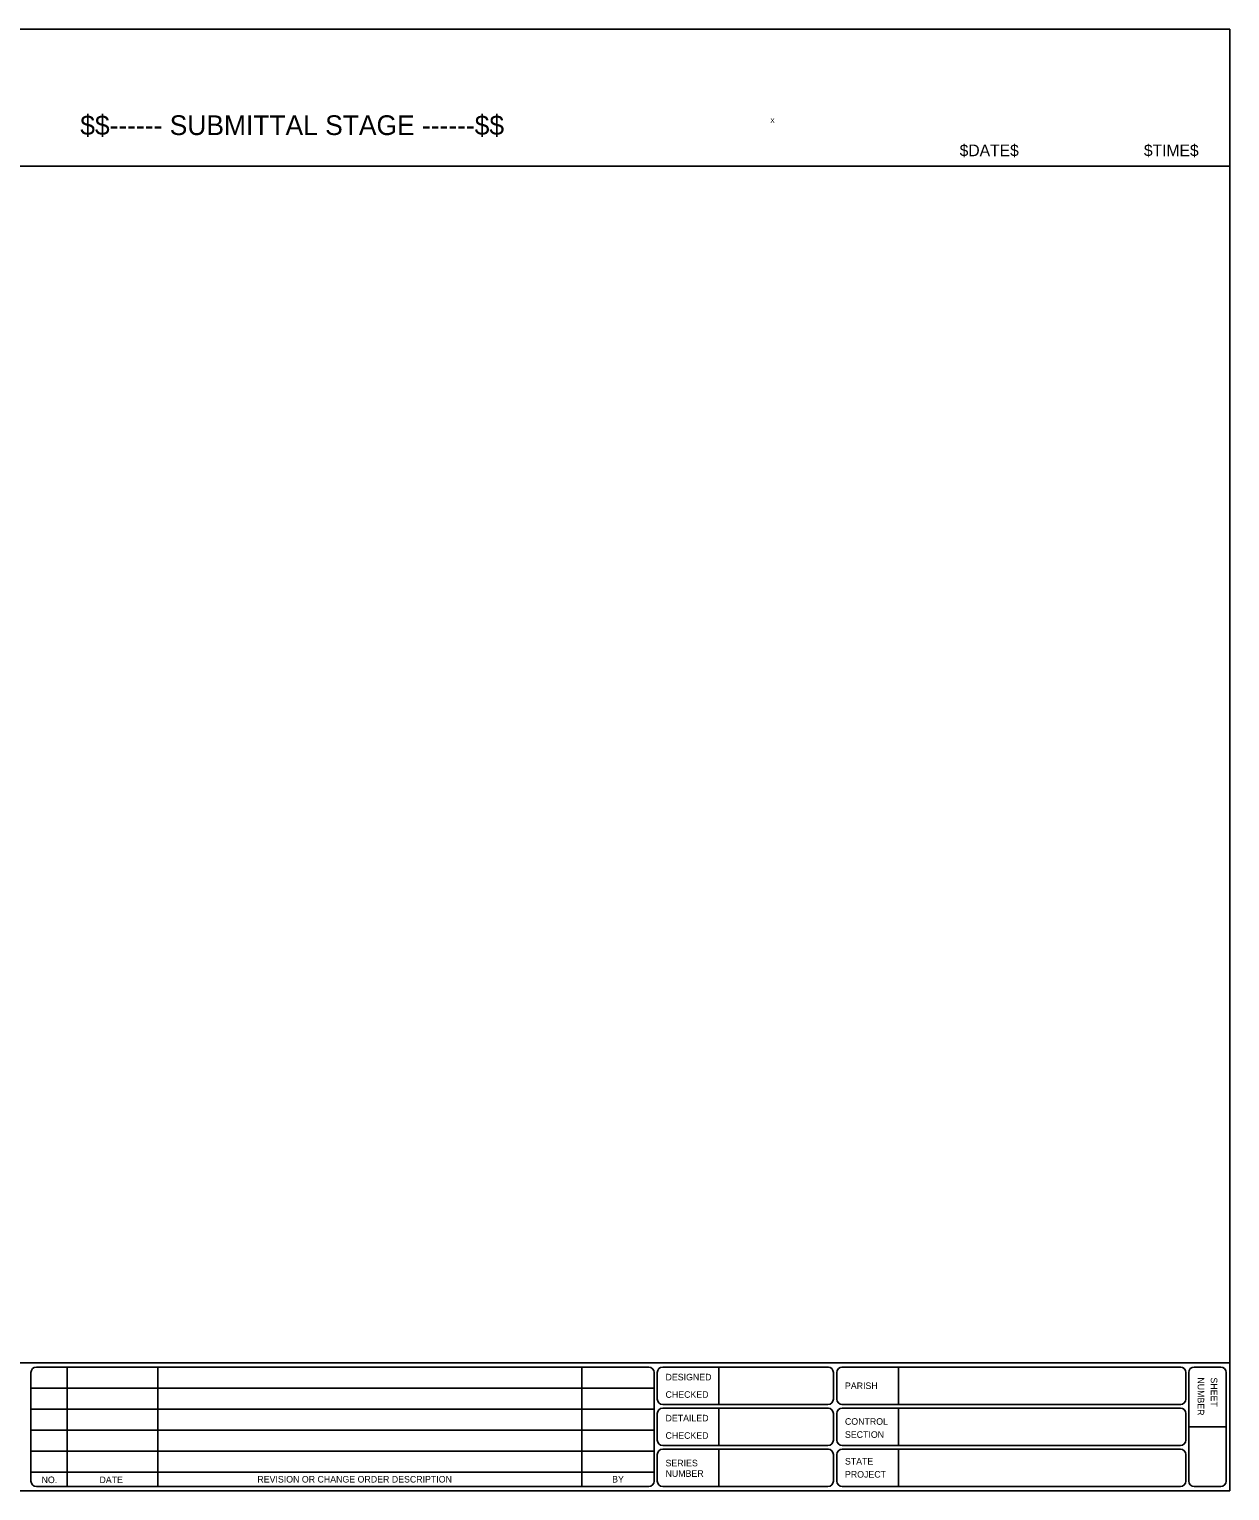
# Model space of a CAD drawing. Extents: x 0 to 1.75, y 0 to 1.33.
# Drawn here: x 0.655 to 1.75, y 0 to 1.333 of the extents above; entities that cross this region are included whole.
import ezdxf

# ---------------------------------------------------------------- set-up
doc = ezdxf.new("R2010")
doc.units = 0
for name, color, linetype in [('Construction Class', 7, 'Continuous'), ('Plot Border', 7, 'Continuous'), ('Sheet Border', 7, 'Continuous')]:
    doc.layers.add(name, color=color, linetype=linetype)

msp = doc.modelspace()

# ---------------------------------------------------------------- linework, layer by layer
at = {"layer": 'Construction Class'}
msp.add_line((1.3333, 1.25), (1.3333, 1.25), dxfattribs=at)
at = {"layer": 'Plot Border'}
msp.add_lwpolyline([(1.75, 0), (1.75, 1.3333), (0, 1.3333), (0, 0)], close=True, dxfattribs=at)
at = {"layer": 'Sheet Border'}
for p, q in [((1.75, 1.2083), (0, 1.2083)), ((1.75, 0), (1.75, 1.2083)), ((1.75, 0.1167), (0, 0.1167)), ((0.6568, 0.1079), (0.6568, 0.0088)), ((1.2202, 0.1128), (0.6618, 0.1128)), ((0.6898, 0.1128), (0.6898, 0.0039)), ((0.7724, 0.1128), (0.7724, 0.0039)), ((1.1591, 0.0039), (1.1591, 0.1128)), ((1.2251, 0.0088), (1.2251, 0.1078)), ((1.228, 0.0836), (1.228, 0.1079)), ((1.384, 0.1128), (1.233, 0.1128)), ((1.2841, 0.0787), (1.2841, 0.1128)), ((1.3886, 0.0836), (1.3886, 0.1079)), ((1.3916, 0.0837), (1.3916, 0.1079)), ((1.7053, 0.1128), (1.3962, 0.1128)), ((1.4478, 0.0787), (1.4478, 0.1128)), ((1.71, 0.0837), (1.71, 0.1079)), ((1.7126, 0.0088), (1.7126, 0.1079)), ((1.7417, 0.1128), (1.7176, 0.1128)), ((1.7467, 0.0088), (1.7467, 0.1079)), ((1.2251, 0.0937), (0.6568, 0.0937)), ((1.2251, 0.0745), (0.6568, 0.0745)), ((1.228, 0.0462), (1.228, 0.0704)), ((1.3836, 0.0787), (1.233, 0.0787)), ((1.384, 0.0754), (1.233, 0.0754)), ((1.2841, 0.0413), (1.2841, 0.0754)), ((1.3886, 0.0462), (1.3886, 0.0704)), ((1.3916, 0.0462), (1.3916, 0.0705)), ((1.7054, 0.0787), (1.3962, 0.0787)), ((1.705, 0.0754), (1.3966, 0.0754)), ((1.4478, 0.0413), (1.4478, 0.0754)), ((1.71, 0.0462), (1.71, 0.0705)), ((1.2251, 0.0554), (0.6568, 0.0554)), ((1.7467, 0.0583), (1.7126, 0.0583)), ((1.3836, 0.0412), (1.233, 0.0412)), ((1.7051, 0.0413), (1.3965, 0.0413)), ((1.2251, 0.0362), (0.6568, 0.0362)), ((1.228, 0.0088), (1.228, 0.033)), ((1.384, 0.0379), (1.233, 0.0379)), ((1.2841, 0.0039), (1.2841, 0.038)), ((1.3886, 0.0088), (1.3886, 0.033)), ((1.3916, 0.0088), (1.3916, 0.033)), ((1.705, 0.038), (1.3966, 0.038)), ((1.4478, 0.0039), (1.4478, 0.038)), ((1.71, 0.0088), (1.71, 0.033)), ((1.2251, 0.0171), (0.6568, 0.0171)), ((1.75, 0), (0, 0)), ((1.2202, 0.0039), (0.6618, 0.0039)), ((1.3836, 0.0038), (1.233, 0.0038)), ((1.705, 0.0039), (1.3966, 0.0039)), ((1.7417, 0.0039), (1.7176, 0.0039))]:
    msp.add_line(p, q, dxfattribs=at)
for centre, start, end in [((0.6618, 0.1079), 90, 180), ((1.2202, 0.1078), 360, 90), ((1.2329, 0.1079), 90, 180), ((1.3836, 0.1079), 360, 90), ((1.3966, 0.1079), 90, 180), ((1.705, 0.1079), 360, 90), ((1.7175, 0.1079), 90, 180), ((1.7418, 0.1079), 360, 90), ((1.2329, 0.0836), 180, 270), ((1.3836, 0.0836), 270, 360), ((1.3966, 0.0837), 180, 270), ((1.705, 0.0837), 270, 360), ((1.2329, 0.0704), 90, 180), ((1.3836, 0.0704), 360, 90), ((1.3966, 0.0705), 90, 180), ((1.705, 0.0705), 360, 90), ((1.2329, 0.0462), 180, 270), ((1.3836, 0.0462), 270, 360), ((1.3966, 0.0462), 180, 270), ((1.705, 0.0462), 270, 360), ((1.2329, 0.033), 90, 180), ((1.3836, 0.033), 360, 90), ((1.3966, 0.033), 90, 180), ((1.705, 0.033), 360, 90), ((0.6618, 0.0088), 180, 270), ((1.2202, 0.0088), 270, 360), ((1.2329, 0.0088), 180, 270), ((1.3836, 0.0088), 270, 360), ((1.3966, 0.0088), 180, 270), ((1.705, 0.0088), 270, 360), ((1.7175, 0.0088), 180, 270), ((1.7418, 0.0088), 270, 360)]:
    msp.add_arc(centre, 0.00495, start, end, dxfattribs=at)

# ---------------------------------------------------------------- texts
at = {"layer": 'Plot Border'}
for s, height, p in [('$$------ SUBMITTAL STAGE ------$$', 0.018, (0.7018, 1.2368)), ('$DATE$', 0.01067, (1.5037, 1.2175)), ('$TIME$', 0.01067, (1.6717, 1.2175))]:
    msp.add_text(s, height=height, rotation=360, dxfattribs=at).set_placement(p)
at = {"layer": 'Sheet Border'}
for s, height, rotation, p in [('X', 0.00417, 360, (1.3311, 1.2479)), ('DESIGNED', 0.006, 360, (1.2355, 0.1007)), ('PARISH', 0.006, 360, (1.3991, 0.0928)), ('NUMBER', 0.006, 270, (1.7207, 0.1034)), ('SHEET', 0.006, 270, (1.7327, 0.1034)), ('CHECKED', 0.006, 360, (1.2355, 0.0848)), ('DETAILED', 0.006, 360, (1.2355, 0.0633)), ('CHECKED', 0.006, 360, (1.2355, 0.0474)), ('CONTROL', 0.006, 360, (1.3991, 0.0602)), ('SECTION', 0.006, 360, (1.3991, 0.0483)), ('SERIES', 0.006, 360, (1.2355, 0.0223)), ('STATE', 0.006, 360, (1.3991, 0.0239)), ('REVISION OR CHANGE ORDER DESCRIPTION', 0.006, 360, (0.8633, 0.0075)), ('BY', 0.006, 360, (1.1868, 0.0075)), ('NUMBER', 0.006, 360, (1.2355, 0.0127)), ('PROJECT', 0.006, 360, (1.3991, 0.012)), ('NO.', 0.006, 360, (0.6665, 0.007)), ('DATE', 0.006, 360, (0.7193, 0.007))]:
    msp.add_text(s, height=height, rotation=rotation, dxfattribs=at).set_placement(p)

doc.saveas('drawing.dxf')
